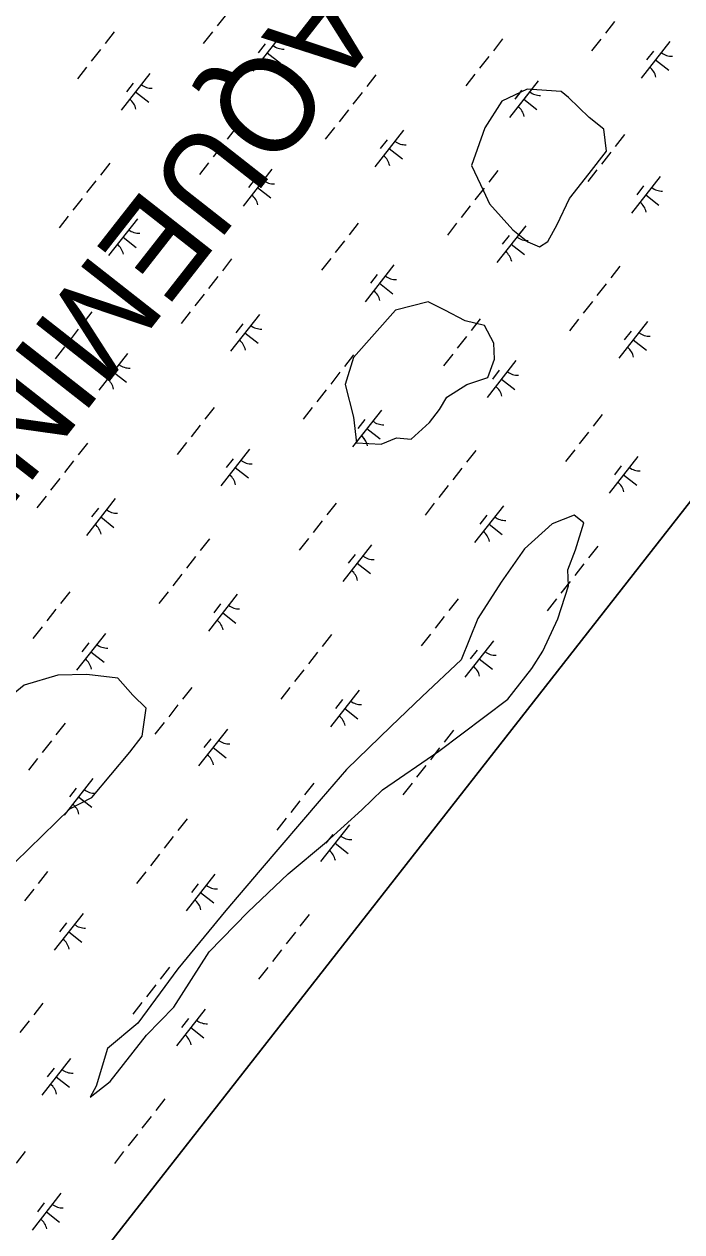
# Model space of a CAD drawing. Extents: x 3896831 to 3918110, y 171006 to 193349.
# Drawn here: x 3914156 to 3914862, y 182329 to 183623 of the extents above; entities that cross this region are included whole.
import ezdxf

# ---------------------------------------------------------------- set-up
doc = ezdxf.new("R2010")
doc.units = 0
for name, color, linetype in [('V-GRID-FRAM', 7, 'Continuous'), ('V-TOPO-GNAM-IDEN', 7, 'Continuous'), ('V-TOPO-SHOR', 7, 'Continuous'), ('V-WETL-SWMP', 7, 'Continuous')]:
    doc.layers.add(name, color=color, linetype=linetype)

msp = doc.modelspace()

# ---------------------------------------------------------------- linework, layer by layer
at = {"layer": 'V-GRID-FRAM'}
msp.add_lwpolyline([(3916044.9, 184610), (3906752.8, 172754.1), (3900055.1, 177809.8), (3909313.3, 189695.8), (3916044.9, 184610)], dxfattribs=at)
at = {"layer": 'V-TOPO-SHOR'}
for points in [[(3914741.2, 183436.6), (3914762.1, 183463.2), (3914780.8, 183487.2), (3914778, 183510.9), (3914762, 183523.4), (3914740.1, 183544.8), (3914732.2, 183551.1), (3914695.7, 183553.9), (3914668.4, 183540.9), (3914650.2, 183512.3), (3914635.8, 183472), (3914648.8, 183444.7), (3914655.2, 183431), (3914680.3, 183402.8), (3914696.3, 183390.2), (3914709, 183384.6), (3914717.9, 183390.5), (3914727.8, 183408.5)], [(3914571.1, 183178.6), (3914590.8, 183196.5), (3914601.6, 183210.3), (3914609.3, 183223.7), (3914631, 183237.2), (3914653.5, 183244.6), (3914660.5, 183264.2), (3914660, 183281.3), (3914649.9, 183300.3), (3914629, 183305.5), (3914607.3, 183316.9), (3914589.2, 183325.6), (3914554.4, 183316.7), (3914509.1, 183266.1), (3914500.2, 183237), (3914509.1, 183202.2), (3914512.4, 183174.6), (3914539.1, 183173.1), (3914555.4, 183179.8)], [(3914600.8, 182844.1), (3914675, 182899.9), (3914700.7, 182932.6), (3914712.4, 182951.1), (3914728.5, 182985.8), (3914739.8, 183021.4), (3914739.2, 183038.5), (3914747.6, 183059.8), (3914756.5, 183088.9), (3914746.2, 183097), (3914722.4, 183087.9), (3914692.9, 183060.9), (3914667.6, 183025.1), (3914642.8, 182986.3), (3914624.7, 182942), (3914582.8, 182902.7), (3914549.3, 182870.6), (3914501.9, 182824.3), (3914474.6, 182793), (3914409.1, 182716.5), (3914372.3, 182673.1), (3914320.6, 182610.8), (3914277.8, 182552.6), (3914245.3, 182525.3), (3914233.1, 182484.9), (3914226.7, 182473.2), (3914248.1, 182489.8), (3914287.2, 182539.7), (3914316.3, 182569.7), (3914354.3, 182628.8), (3914395.9, 182671.3), (3914439.2, 182712.4), (3914480.2, 182746.9), (3914518.1, 182781.1), (3914540.4, 182802.5)], [(3914146.3, 182725.1), (3914204.8, 182782.1), (3914228.3, 182794.3), (3914269.1, 182842.9), (3914282.6, 182860.1), (3914286.8, 182890.2), (3914272.6, 182904), (3914256.4, 182922.3), (3914223.2, 182926.1), (3914192.1, 182925.4), (3914156, 182914.8), (3914126.2, 182891), (3914094.6, 182843.5), (3914069.8, 182790.7), (3914063.7, 182751), (3914044.6, 182715.9), (3914024.9, 182673), (3914001.3, 182635.9), (3913988.6, 182612.6), (3913998.7, 182593.5), (3914016.9, 182584.8), (3914040.2, 182611), (3914067.5, 182642.4), (3914103, 182684.1)]]:
    msp.add_lwpolyline(points, close=True, dxfattribs=at)
at = {"layer": 'V-WETL-SWMP'}
for p, q in [((3910067.8, 176983.8), (3916044.9, 184610)), ((3914372.8, 183634.1), (3914362.9, 183621.5)), ((3914789.4, 183626.4), (3914779.6, 183613.8)), ((3914252.5, 183615.3), (3914242.7, 183602.7)), ((3914358, 183615.2), (3914348.1, 183602.6)), ((3914432.1, 183612.4), (3914401.3, 183573.1)), ((3914414.3, 183602.2), (3914406.9, 183592.8)), ((3914669.2, 183607.6), (3914659.3, 183595)), ((3914774.6, 183607.5), (3914764.8, 183594.9)), ((3914848.8, 183604.7), (3914817.9, 183565.4)), ((3914237.7, 183596.4), (3914227.9, 183583.8)), ((3914416.7, 183592.8), (3914430.9, 183581.7)), ((3914654.4, 183588.7), (3914644.5, 183576.1)), ((3914831, 183594.5), (3914823.6, 183585.1)), ((3914833.4, 183585.1), (3914847.5, 183574)), ((3914222.9, 183577.5), (3914213.1, 183564.9)), ((3914290.7, 183570.5), (3914259.9, 183531.1)), ((3914272.9, 183560.3), (3914265.5, 183550.8)), ((3914533.3, 183569.2), (3914523.5, 183556.6)), ((3914639.6, 183569.8), (3914629.7, 183557.2)), ((3914707.4, 183562.8), (3914676.5, 183523.4)), ((3914275.3, 183550.8), (3914289.5, 183539.7)), ((3914518.5, 183550.3), (3914508.7, 183537.7)), ((3914700.1, 183553.5), (3914676.5, 183523.4)), ((3914689.6, 183552.6), (3914682.2, 183543.1)), ((3914687.6, 183550), (3914682.2, 183543.1)), ((3914692, 183543.1), (3914706.1, 183532)), ((3914692, 183543.1), (3914706.1, 183532)), ((3914503.7, 183531.5), (3914493.8, 183518.9)), ((3914383.5, 183512.7), (3914373.6, 183500.1)), ((3914488.9, 183512.6), (3914479, 183500)), ((3914563, 183509.8), (3914532.2, 183470.5)), ((3914368.6, 183493.8), (3914358.8, 183481.2)), ((3914545.3, 183499.6), (3914537.9, 183490.2)), ((3914800.1, 183505), (3914790.2, 183492.4)), ((3914547.6, 183490.2), (3914561.8, 183479)), ((3914785.3, 183486.1), (3914775.4, 183473.5)), ((3914247.6, 183474.3), (3914237.7, 183461.7)), ((3914353.8, 183474.9), (3914344, 183462.3)), ((3914421.7, 183467.9), (3914390.8, 183428.5)), ((3914770.5, 183467.2), (3914760.6, 183454.6)), ((3914232.8, 183455.4), (3914222.9, 183442.8)), ((3914403.9, 183457.7), (3914396.5, 183448.2)), ((3914664.2, 183466.6), (3914654.4, 183454)), ((3914664.2, 183466.6), (3914654.4, 183454)), ((3914838.3, 183460.2), (3914807.5, 183420.8)), ((3914406.2, 183448.2), (3914420.4, 183437.1)), ((3914649.4, 183447.7), (3914639.6, 183435.1)), ((3914649.4, 183447.7), (3914648.1, 183446)), ((3914820.5, 183450), (3914813.1, 183440.5)), ((3914218, 183436.5), (3914208.1, 183423.9)), ((3914634.6, 183428.8), (3914624.8, 183416.3)), ((3914822.9, 183440.5), (3914837, 183429.4)), ((3914203.2, 183417.7), (3914193.3, 183405.1)), ((3914277.3, 183414.9), (3914246.5, 183375.6)), ((3914259.5, 183404.7), (3914252.1, 183395.3)), ((3914514.4, 183410.1), (3914504.5, 183397.5)), ((3914619.8, 183410), (3914610, 183397.4)), ((3914694, 183407.2), (3914663.1, 183367.9)), ((3914694, 183407.2), (3914686.6, 183397.8)), ((3914261.9, 183395.2), (3914276.1, 183384.1)), ((3914499.6, 183391.2), (3914489.7, 183378.6)), ((3914676.2, 183397), (3914668.8, 183387.6)), ((3914678.5, 183387.5), (3914692.7, 183376.4)), ((3914378.5, 183371.7), (3914368.7, 183359.1)), ((3914484.8, 183372.3), (3914474.9, 183359.7)), ((3914552.6, 183365.3), (3914521.7, 183325.9)), ((3914795.2, 183364), (3914785.3, 183351.4)), ((3914363.7, 183352.8), (3914353.8, 183340.2)), ((3914534.8, 183355.1), (3914527.4, 183345.6)), ((3914537.2, 183345.6), (3914551.3, 183334.5)), ((3914780.4, 183345.1), (3914770.5, 183332.5)), ((3914348.9, 183333.9), (3914339, 183321.3)), ((3914765.6, 183326.2), (3914755.7, 183313.6)), ((3914228.6, 183315.2), (3914218.8, 183302.6)), ((3914334.1, 183315), (3914324.2, 183302.5)), ((3914408.2, 183312.3), (3914377.4, 183273)), ((3914390.4, 183302.1), (3914383, 183292.7)), ((3914645.3, 183307.5), (3914635.4, 183294.9)), ((3914641.3, 183302.4), (3914635.4, 183294.9)), ((3914750.8, 183307.3), (3914740.9, 183294.8)), ((3914824.9, 183304.6), (3914794, 183265.3)), ((3914213.8, 183296.3), (3914204, 183283.7)), ((3914392.8, 183292.6), (3914407, 183281.5)), ((3914630.5, 183288.6), (3914620.6, 183276)), ((3914630.5, 183288.6), (3914620.6, 183276)), ((3914807.1, 183294.4), (3914799.7, 183285)), ((3914199, 183277.4), (3914189.2, 183264.8)), ((3914809.5, 183284.9), (3914823.6, 183273.8)), ((3914266.9, 183270.4), (3914236, 183231)), ((3914249.1, 183260.2), (3914241.7, 183250.7)), ((3914509.4, 183269.1), (3914499.6, 183256.5)), ((3914615.7, 183269.7), (3914605.8, 183257.1)), ((3914615.7, 183269.7), (3914605.8, 183257.1)), ((3914683.5, 183262.7), (3914652.7, 183223.3)), ((3914251.4, 183250.7), (3914265.6, 183239.6)), ((3914494.6, 183250.2), (3914484.8, 183237.6)), ((3914665.7, 183252.5), (3914658.3, 183243)), ((3914668.1, 183243), (3914682.2, 183231.9)), ((3914479.8, 183231.3), (3914470, 183218.7)), ((3914359.6, 183212.6), (3914349.7, 183200)), ((3914465, 183212.4), (3914455.2, 183199.8)), ((3914539.2, 183209.7), (3914508.3, 183170.3)), ((3914539.2, 183209.7), (3914512.3, 183175.5)), ((3914521.4, 183199.5), (3914514, 183190.1)), ((3914521.4, 183199.5), (3914514, 183190.1)), ((3914776.2, 183204.9), (3914766.3, 183192.3)), ((3914344.8, 183193.7), (3914334.9, 183181.1)), ((3914523.7, 183190), (3914537.9, 183178.9)), ((3914523.7, 183190), (3914537.9, 183178.9)), ((3914761.4, 183186), (3914751.5, 183173.4)), ((3914223.7, 183174.2), (3914213.8, 183161.6)), ((3914330, 183174.8), (3914320.1, 183162.2)), ((3914397.8, 183167.8), (3914366.9, 183128.4)), ((3914380, 183157.6), (3914372.6, 183148.1)), ((3914640.4, 183166.5), (3914630.5, 183153.9)), ((3914746.6, 183167.1), (3914736.7, 183154.5)), ((3914814.4, 183160.1), (3914783.6, 183120.7)), ((3914208.9, 183155.3), (3914199, 183142.7)), ((3914382.3, 183148.1), (3914396.5, 183137)), ((3914625.6, 183147.6), (3914615.7, 183135)), ((3914796.6, 183149.9), (3914789.2, 183140.4)), ((3914194.1, 183136.4), (3914184.2, 183123.8)), ((3914799, 183140.4), (3914813.2, 183129.3)), ((3914610.8, 183128.7), (3914600.9, 183116.1)), ((3914179.3, 183117.5), (3914169.4, 183104.9)), ((3914253.4, 183114.8), (3914222.6, 183075.4)), ((3914490.5, 183110), (3914480.6, 183097.4)), ((3914595.9, 183109.8), (3914586.1, 183097.2)), ((3914670.1, 183107.1), (3914639.2, 183067.7)), ((3914235.6, 183104.6), (3914228.2, 183095.2)), ((3914238, 183095.1), (3914252.2, 183084)), ((3914652.3, 183096.9), (3914644.9, 183087.5)), ((3914475.7, 183091.1), (3914465.8, 183078.5)), ((3914654.7, 183087.4), (3914668.8, 183076.3)), ((3914354.6, 183071.6), (3914344.8, 183059)), ((3914460.9, 183072.2), (3914451, 183059.6)), ((3914528.7, 183065.1), (3914497.8, 183025.8)), ((3914510.9, 183054.9), (3914503.5, 183045.5)), ((3914771.3, 183063.9), (3914761.4, 183051.3)), ((3914339.8, 183052.7), (3914330, 183040.1)), ((3914513.3, 183045.5), (3914527.4, 183034.4)), ((3914756.5, 183045), (3914746.6, 183032.4)), ((3914325, 183033.8), (3914315.2, 183021.2)), ((3914204.8, 183015), (3914194.9, 183002.5)), ((3914310.2, 183014.9), (3914300.4, 183002.3)), ((3914741.7, 183026.1), (3914731.8, 183013.5)), ((3914739.7, 183023.6), (3914731.8, 183013.5)), ((3914384.4, 183012.2), (3914353.5, 182972.8)), ((3914366.6, 183002), (3914359.2, 182992.5)), ((3914621.4, 183007.4), (3914611.5, 182994.8)), ((3914726.9, 183007.2), (3914717, 182994.6)), ((3914726.9, 183007.2), (3914717, 182994.6)), ((3914190, 182996.2), (3914180.1, 182983.6)), ((3914368.9, 182992.5), (3914383.1, 182981.4)), ((3914606.6, 182988.5), (3914596.7, 182975.9)), ((3914175.1, 182977.3), (3914165.3, 182964.7)), ((3914243, 182970.2), (3914212.1, 182930.9)), ((3914485.6, 182969), (3914475.7, 182956.4)), ((3914591.8, 182969.6), (3914581.9, 182957)), ((3914659.6, 182962.5), (3914628.8, 182923.2)), ((3914659.6, 182962.5), (3914628.8, 182923.2)), ((3914225.2, 182960), (3914217.8, 182950.6)), ((3914227.5, 182950.6), (3914241.7, 182939.5)), ((3914470.7, 182950.1), (3914460.9, 182937.5)), ((3914641.8, 182952.3), (3914634.4, 182942.9)), ((3914641.8, 182952.3), (3914634.4, 182942.9)), ((3914644.2, 182942.9), (3914658.4, 182931.8)), ((3914644.2, 182942.9), (3914658.4, 182931.8)), ((3914455.9, 182931.2), (3914446.1, 182918.6)), ((3914335.7, 182912.4), (3914325.8, 182899.8)), ((3914441.1, 182912.3), (3914431.3, 182899.7)), ((3914515.3, 182909.6), (3914484.4, 182870.2)), ((3914497.5, 182899.4), (3914490.1, 182889.9)), ((3914320.9, 182893.6), (3914311, 182881)), ((3914499.9, 182889.9), (3914514, 182878.8)), ((3914199.8, 182874.1), (3914190, 182861.5)), ((3914199.8, 182874.1), (3914190, 182861.5)), ((3914306.1, 182874.7), (3914296.2, 182862.1)), ((3914373.9, 182867.6), (3914343, 182828.3)), ((3914616.5, 182866.4), (3914606.6, 182853.8)), ((3914616.5, 182866.4), (3914606.6, 182853.8)), ((3914185, 182855.2), (3914175.2, 182842.6)), ((3914185, 182855.2), (3914175.2, 182842.6)), ((3914356.1, 182857.4), (3914348.7, 182848)), ((3914358.5, 182847.9), (3914372.6, 182836.8)), ((3914601.7, 182847.5), (3914591.8, 182834.9)), ((3914601.7, 182847.5), (3914597, 182841.5)), ((3914170.2, 182836.3), (3914160.4, 182823.7)), ((3914170.2, 182836.3), (3914160.4, 182823.7)), ((3914586.9, 182828.6), (3914577, 182816)), ((3914229.5, 182814.7), (3914198.7, 182775.3)), ((3914229.5, 182814.7), (3914201.4, 182778.8)), ((3914466.6, 182809.8), (3914456.7, 182797.2)), ((3914572.1, 182809.7), (3914562.2, 182797.1)), ((3914211.8, 182804.5), (3914204.4, 182795)), ((3914211.8, 182804.5), (3914204.4, 182795)), ((3914214.1, 182795), (3914228.3, 182783.9)), ((3914214.1, 182795), (3914220.3, 182790.1)), ((3914451.8, 182790.9), (3914441.9, 182778.4)), ((3914330.7, 182771.5), (3914320.9, 182758.9)), ((3914437, 182772.1), (3914427.1, 182759.5)), ((3914504.8, 182765), (3914474, 182725.7)), ((3914315.9, 182752.6), (3914306.1, 182740)), ((3914487, 182754.8), (3914479.6, 182745.4)), ((3914487, 182754.8), (3914482.4, 182749)), ((3914489.4, 182745.3), (3914503.5, 182734.2)), ((3914301.1, 182733.7), (3914291.3, 182721.1)), ((3914180.9, 182714.9), (3914171, 182702.3)), ((3914286.3, 182714.8), (3914276.5, 182702.2)), ((3914360.5, 182712.1), (3914329.6, 182672.7)), ((3914166.1, 182696), (3914156.2, 182683.4)), ((3914342.7, 182701.9), (3914335.3, 182692.4)), ((3914345, 182692.4), (3914359.2, 182681.3)), ((3914219.1, 182670.1), (3914188.2, 182630.8)), ((3914461.7, 182668.9), (3914451.8, 182656.3)), ((3914201.3, 182659.9), (3914193.9, 182650.5)), ((3914203.7, 182650.4), (3914217.8, 182639.3)), ((3914446.9, 182650), (3914437, 182637.4)), ((3914432.1, 182631.1), (3914422.2, 182618.5)), ((3914311.8, 182612.3), (3914301.9, 182599.7)), ((3914417.3, 182612.2), (3914407.4, 182599.6)), ((3914297, 182593.4), (3914287.1, 182580.8)), ((3914175.9, 182573.9), (3914166.1, 182561.4)), ((3914282.2, 182574.5), (3914272.3, 182561.9)), ((3914350, 182567.5), (3914319.2, 182528.1)), ((3914161.1, 182555.1), (3914151.3, 182542.5)), ((3914332.2, 182557.3), (3914324.8, 182547.9)), ((3914334.6, 182547.8), (3914348.7, 182536.7)), ((3914205.7, 182514.5), (3914174.8, 182475.2)), ((3914187.9, 182504.3), (3914180.5, 182494.9)), ((3914190.2, 182494.9), (3914204.4, 182483.8)), ((3914306.9, 182471.3), (3914297, 182458.7)), ((3914292.1, 182452.4), (3914282.2, 182439.9)), ((3914277.3, 182433.6), (3914267.4, 182421)), ((3914157, 182414.8), (3914147.1, 182402.2)), ((3914262.4, 182414.7), (3914252.6, 182402.1)), ((3914195.2, 182370), (3914164.3, 182330.6)), ((3914177.4, 182359.8), (3914170, 182350.3)), ((3914179.8, 182350.3), (3914193.9, 182339.2))]:
    msp.add_line(p, q, dxfattribs=at)
for points in [[(3914741.2, 183436.6), (3914762.1, 183463.2), (3914780.8, 183487.2), (3914778, 183510.9), (3914762, 183523.4), (3914740.1, 183544.8), (3914732.2, 183551.1), (3914695.7, 183553.9), (3914668.4, 183540.9), (3914650.2, 183512.3), (3914635.8, 183472), (3914648.8, 183444.7), (3914655.2, 183431), (3914680.3, 183402.8), (3914696.3, 183390.2), (3914709, 183384.6), (3914717.9, 183390.5), (3914727.8, 183408.5)], [(3914571.1, 183178.6), (3914590.8, 183196.5), (3914601.6, 183210.3), (3914609.3, 183223.7), (3914631, 183237.2), (3914653.5, 183244.6), (3914660.5, 183264.2), (3914660, 183281.3), (3914649.9, 183300.3), (3914629, 183305.5), (3914607.3, 183316.9), (3914589.2, 183325.6), (3914554.4, 183316.7), (3914509.1, 183266.1), (3914500.2, 183237), (3914509.1, 183202.2), (3914512.4, 183174.6), (3914539.1, 183173.1), (3914555.4, 183179.8)], [(3914600.8, 182844.1), (3914675, 182899.9), (3914700.7, 182932.6), (3914712.4, 182951.1), (3914728.5, 182985.8), (3914739.8, 183021.4), (3914739.2, 183038.5), (3914747.6, 183059.8), (3914756.5, 183088.9), (3914746.2, 183097), (3914722.4, 183087.9), (3914692.9, 183060.9), (3914667.6, 183025.1), (3914642.8, 182986.3), (3914624.7, 182942), (3914582.8, 182902.7), (3914549.3, 182870.6), (3914501.9, 182824.3), (3914474.6, 182793), (3914409.1, 182716.5), (3914372.3, 182673.1), (3914320.6, 182610.8), (3914277.8, 182552.6), (3914245.3, 182525.3), (3914233.1, 182484.9), (3914226.7, 182473.2), (3914248.1, 182489.8), (3914287.2, 182539.7), (3914316.3, 182569.7), (3914354.3, 182628.8), (3914395.9, 182671.3), (3914439.2, 182712.4), (3914480.2, 182746.9), (3914518.1, 182781.1), (3914540.4, 182802.5)], [(3914146.3, 182725.1), (3914204.8, 182782.1), (3914228.3, 182794.3), (3914269.1, 182842.9), (3914282.6, 182860.1), (3914286.8, 182890.2), (3914272.6, 182904), (3914256.4, 182922.3), (3914223.2, 182926.1), (3914192.1, 182925.4), (3914156, 182914.8), (3914126.2, 182891), (3914094.6, 182843.5), (3914069.8, 182790.7), (3914063.7, 182751), (3914044.6, 182715.9), (3914024.9, 182673), (3914001.3, 182635.9), (3913988.6, 182612.6), (3913998.7, 182593.5), (3914016.9, 182584.8), (3914040.2, 182611), (3914067.5, 182642.4), (3914103, 182684.1)]]:
    msp.add_lwpolyline(points, close=True, dxfattribs=at)
for centre, start, end in [((3914433.9, 183614.4), 231.1403, 272.6839), ((3914399.9, 183570.9), 11.1403, 52.6839), ((3914850.6, 183606.7), 231.1403, 272.6839), ((3914816.5, 183563.2), 11.1403, 52.6839), ((3914292.5, 183572.4), 231.1403, 272.6839), ((3914709.2, 183564.7), 231.1403, 272.6839), ((3914709.2, 183564.7), 231.1403, 272.6839), ((3914258.5, 183528.9), 11.1403, 52.6839), ((3914675.1, 183521.2), 11.1403, 52.6839), ((3914675.1, 183521.2), 11.1403, 52.6839), ((3914564.9, 183511.7), 231.1403, 272.6839), ((3914530.8, 183468.3), 11.1403, 52.6839), ((3914423.5, 183469.8), 231.1403, 272.6839), ((3914840.1, 183462.1), 231.1403, 272.6839), ((3914389.4, 183426.3), 11.1403, 52.6839), ((3914806, 183418.6), 11.1403, 52.6839), ((3914279.1, 183416.8), 231.1403, 272.6839), ((3914695.8, 183409.1), 231.1403, 272.6839), ((3914695.8, 183409.1), 266.2426, 272.6839), ((3914245.1, 183373.4), 11.1403, 52.6839), ((3914661.7, 183365.7), 11.1403, 52.6839), ((3914554.4, 183367.2), 231.1403, 272.6839), ((3914520.3, 183323.7), 11.1403, 52.6839), ((3914410, 183314.2), 231.1403, 272.6839), ((3914826.7, 183306.5), 231.1403, 272.6839), ((3914376, 183270.7), 11.1403, 52.6839), ((3914792.6, 183263), 11.1403, 52.6839), ((3914268.7, 183272.3), 231.1403, 272.6839), ((3914685.3, 183264.6), 231.1403, 272.6839), ((3914234.6, 183228.8), 11.1403, 52.6839), ((3914651.2, 183221.1), 11.1403, 52.6839), ((3914541, 183211.6), 231.1403, 272.6839), ((3914541, 183211.6), 231.1403, 272.6839), ((3914506.9, 183168.1), 11.1403, 52.6839), ((3914506.9, 183168.1), 19.3364, 52.6839), ((3914399.6, 183169.7), 231.1403, 272.6839), ((3914816.2, 183162), 231.1403, 272.6839), ((3914365.5, 183126.2), 11.1403, 52.6839), ((3914782.1, 183118.5), 11.1403, 52.6839), ((3914255.2, 183116.7), 231.1403, 272.6839), ((3914671.9, 183109), 231.1403, 272.6839), ((3914221.2, 183073.2), 11.1403, 52.6839), ((3914637.8, 183065.5), 11.1403, 52.6839), ((3914530.5, 183067.1), 231.1403, 272.6839), ((3914496.4, 183023.6), 11.1403, 52.6839), ((3914386.2, 183014.1), 231.1403, 272.6839), ((3914352.1, 182970.6), 11.1403, 52.6839), ((3914244.8, 182972.2), 231.1403, 272.6839), ((3914661.4, 182964.5), 231.1403, 272.6839), ((3914661.4, 182964.5), 231.1403, 272.6839), ((3914210.7, 182928.7), 11.1403, 52.6839), ((3914627.3, 182921), 11.1403, 52.6839), ((3914627.3, 182921), 11.1403, 52.6839), ((3914517.1, 182911.5), 231.1403, 272.6839), ((3914483, 182868), 11.1403, 52.6839), ((3914375.7, 182869.5), 231.1403, 272.6839), ((3914341.6, 182826.1), 11.1403, 52.6839), ((3914231.4, 182816.6), 231.1403, 272.6839), ((3914231.4, 182816.6), 231.1403, 272.6839), ((3914197.3, 182773.1), 11.1403, 52.6839), ((3914197.3, 182773.1), 42.2406, 52.6839), ((3914506.6, 182766.9), 231.1403, 272.6839), ((3914472.5, 182723.5), 11.1403, 52.6839), ((3914362.3, 182714), 231.1403, 272.6839), ((3914328.2, 182670.5), 11.1403, 52.6839), ((3914220.9, 182672), 231.1403, 272.6839), ((3914186.8, 182628.5), 11.1403, 52.6839), ((3914351.8, 182569.4), 231.1403, 272.6839), ((3914317.7, 182525.9), 11.1403, 52.6839), ((3914207.5, 182516.5), 231.1403, 272.6839), ((3914173.4, 182473), 11.1403, 52.6839), ((3914197, 182371.9), 231.1403, 272.6839), ((3914162.9, 182328.4), 11.1403, 52.6839)]:
    msp.add_arc(centre, 17.6, start, end, dxfattribs=at)

# ---------------------------------------------------------------- texts
at = {"layer": 'V-TOPO-GNAM-IDEN'}
msp.add_text('PLAQUEMINES', height=100, rotation=231.8952, dxfattribs=at).set_placement((3914565.5, 183807.9))

doc.saveas('drawing.dxf')
